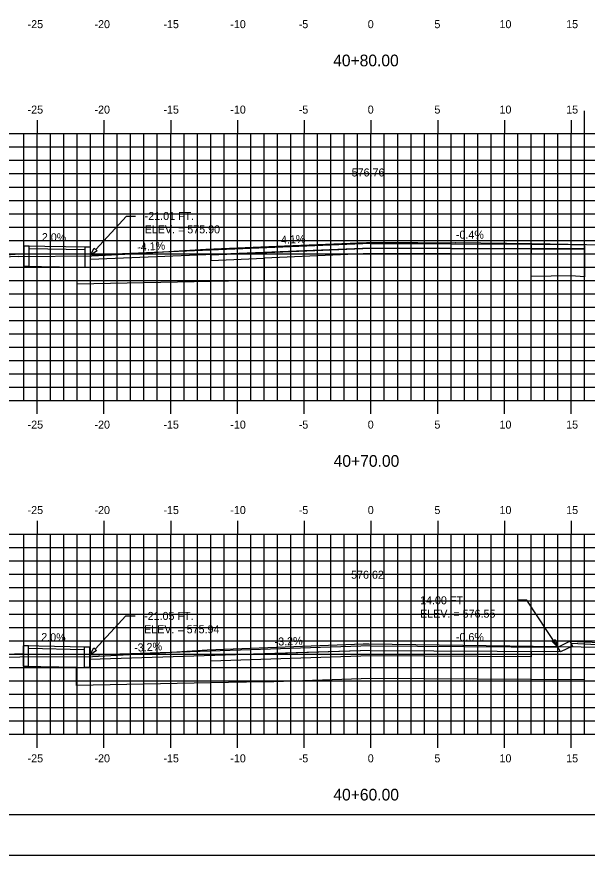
# Model space of a CAD drawing. Extents: x 1048345 to 1048515, y 781148 to 781258.
# Drawn here: x 1048401.3 to 1048444, y 781148.2 to 781211 of the extents above; entities that cross this region are included whole.
import ezdxf

# ---------------------------------------------------------------- set-up
doc = ezdxf.new("R2010")
doc.units = 0
for name, color, linetype in [('ANNOTATION', 7, 'Continuous'), ('BORDER', 7, 'Continuous'), ('D_Curb_Type1_Lt', 7, 'Continuous'), ('D_Curb_Type_5_Rt', 7, 'Continuous'), ('D_Roadway_Centerline', 7, 'Continuous'), ('D_Roadway_Centerline_Text', 7, 'Continuous'), ('D_Roadway_Edge_Shoulder', 7, 'Continuous'), ('D_Roadway_Edge_TW', 7, 'Continuous'), ('D_Roadway_Pavement', 7, 'Continuous'), ('D_Roadway_Sidewalks_Paved', 7, 'Continuous'), ('D_Roadway_SubGrade', 7, 'Continuous'), ('D_Text_Standard', 7, 'Continuous'), ('E_ROW_Line', 7, 'Continuous'), ('H_V ANNOTATION', 7, 'Continuous'), ('MAJOR', 7, 'Continuous'), ('MINOR', 7, 'Continuous'), ('PLOT BOUNDARY', 7, 'Continuous'), ('S_Roadway_Centerline', 7, 'Continuous')]:
    doc.layers.add(name, color=color, linetype=linetype)

msp = doc.modelspace()

# ---------------------------------------------------------------- linework, layer by layer
at = {"layer": 'BORDER'}
msp.add_lwpolyline([(1048352.833, 781151.252), (1048512.833, 781151.252), (1048512.833, 781256.252), (1048352.833, 781256.252)], close=True, dxfattribs=at)
at = {"layer": 'D_Curb_Type1_Lt'}
for points in [[(1048401.824, 781193.83), (1048401.824, 781192.33), (1048402.241, 781192.33), (1048402.241, 781193.83)], [(1048406.406, 781193.736), (1048406.406, 781192.236), (1048406.823, 781192.236), (1048406.823, 781193.736)], [(1048406.406, 781193.736), (1048406.406, 781192.236), (1048406.823, 781192.236), (1048406.823, 781193.736)], [(1048401.78, 781163.869), (1048401.78, 781162.369), (1048402.196, 781162.369), (1048402.196, 781163.869)], [(1048406.362, 781163.775), (1048406.362, 781162.275), (1048406.779, 781162.275), (1048406.779, 781163.775)]]:
    msp.add_lwpolyline(points, close=True, dxfattribs=at)
at = {"layer": 'D_Curb_Type_5_Rt'}
msp.add_lwpolyline([(1048441.832, 781163.792), (1048442.727, 781164.24), (1048442.913, 781163.867), (1048442.019, 781163.42)], close=True, dxfattribs=at)
at = {"layer": 'D_Roadway_Edge_Shoulder'}
for p, q in [((1048427.832, 781194.011), (1048406.824, 781193.152)), ((1048427.832, 781193.678), (1048406.825, 781192.819))]:
    msp.add_line(p, q, dxfattribs=at)
msp.add_lwpolyline([(1048439.832, 781193.963), (1048442.832, 781193.951), (1048443.832, 781193.947), (1048443.832, 781193.614), (1048442.832, 781193.618), (1048439.832, 781193.63)], close=True, dxfattribs=at)
at = {"layer": 'D_Roadway_Edge_TW'}
for p, q in [((1048427.832, 781163.874), (1048406.785, 781163.192)), ((1048427.832, 781163.541), (1048406.785, 781162.859)), ((1048427.832, 781163.874), (1048441.832, 781163.792)), ((1048427.832, 781163.541), (1048441.999, 781163.458))]:
    msp.add_line(p, q, dxfattribs=at)
msp.add_lwpolyline([(1048427.832, 781194.011), (1048439.832, 781193.963), (1048439.832, 781193.63), (1048427.832, 781193.678)], dxfattribs=at)
at = {"layer": 'D_Roadway_Pavement'}
for p, q in [((1048427.832, 781163.541), (1048415.832, 781163.152)), ((1048401.78, 781163.286), (1048396.063, 781163.02))]:
    msp.add_line(p, q, dxfattribs=at)
for points in [[(1048415.832, 781192.757), (1048415.832, 781193.174), (1048427.832, 781193.678), (1048439.832, 781193.63), (1048439.832, 781193.213), (1048427.832, 781193.261), (1048419.832, 781192.925)], [(1048439.832, 781163.471), (1048439.832, 781163.064), (1048427.832, 781163.124)], [(1048427.832, 781163.124), (1048415.832, 781162.735), (1048415.832, 781163.152)], [(1048415.832, 781162.735), (1048415.832, 781163.121)]]:
    msp.add_lwpolyline(points, dxfattribs=at)
at = {"layer": 'D_Roadway_Sidewalks_Paved'}
for points in [[(1048406.523, 781193.736), (1048401.824, 781193.83), (1048401.824, 781193.663)], [(1048406.523, 781193.736), (1048401.824, 781193.83), (1048401.824, 781193.663)], [(1048402.241, 781193.655), (1048406.406, 781193.571)], [(1048402.241, 781193.655), (1048406.406, 781193.571)], [(1048406.479, 781163.775), (1048401.78, 781163.869), (1048401.78, 781163.703)], [(1048402.196, 781163.694), (1048406.362, 781163.611)]]:
    msp.add_lwpolyline(points, dxfattribs=at)
at = {"layer": 'D_Roadway_SubGrade'}
for p, q in [((1048401.824, 781193.83), (1048401.824, 781192.33)), ((1048443.832, 781193.947), (1048443.832, 781191.521)), ((1048401.824, 781193.246), (1048397.06, 781192.89)), ((1048401.824, 781192.33), (1048405.824, 781192.25)), ((1048405.825, 781192.064), (1048405.824, 781192.25)), ((1048442.727, 781164.24), (1048446.775, 781164.052)), ((1048443.832, 781163.262), (1048443.832, 781164.054)), ((1048401.78, 781163.869), (1048401.78, 781162.369)), ((1048401.78, 781162.369), (1048405.78, 781162.289)), ((1048405.786, 781162.099), (1048405.78, 781162.289))]:
    msp.add_line(p, q, dxfattribs=at)
for points in [[(1048443.832, 781191.521), (1048442.832, 781191.595), (1048439.832, 781191.547), (1048439.832, 781193.63), (1048439.832, 781193.63), (1048442.832, 781193.618), (1048443.832, 781193.614), (1048443.832, 781193.031)], [(1048415.832, 781193.174), (1048415.832, 781192.757), (1048419.832, 781192.925), (1048419.832, 781191.259), (1048415.832, 781191.179), (1048405.825, 781190.978), (1048405.825, 781192.064)], [(1048442.814, 781164.072), (1048446.768, 781163.889)], [(1048419.832, 781161.177), (1048427.832, 781161.457), (1048443.832, 781161.364), (1048443.832, 781163.262)], [(1048419.832, 781161.177), (1048415.832, 781161.097), (1048405.786, 781160.896), (1048405.786, 781162.099)]]:
    msp.add_lwpolyline(points, dxfattribs=at)
at = {"layer": 'D_Text_Standard'}
for points in [[(1048407.219, 781193.58), (1048409.525, 781196.08), (1048410.205, 781196.08)], [(1048441.832, 781163.792), (1048439.515, 781167.292), (1048438.835, 781167.292)], [(1048407.174, 781163.62), (1048409.481, 781166.12), (1048410.161, 781166.12)]]:
    msp.add_lwpolyline(points, dxfattribs=at)
for points in [[(1048406.824, 781193.152), (1048407.112, 781193.679), (1048407.326, 781193.481)], [(1048441.832, 781163.792), (1048441.39, 781164.197), (1048441.632, 781164.358)], [(1048406.78, 781163.192), (1048407.067, 781163.718), (1048407.281, 781163.521)]]:
    msp.add_lwpolyline(points, close=True, dxfattribs=at)
at = {"layer": 'E_ROW_Line'}
msp.add_line((1048443.832, 781193.947), (1048443.832, 781203.947), dxfattribs=at)
at = {"layer": 'MAJOR'}
for p, q in [((1048402.832, 781203.254), (1048402.832, 781202.252)), ((1048407.832, 781203.254), (1048407.832, 781202.252)), ((1048412.832, 781203.254), (1048412.832, 781202.252)), ((1048417.832, 781203.254), (1048417.832, 781202.252)), ((1048422.832, 781203.254), (1048422.832, 781202.252)), ((1048427.832, 781203.254), (1048427.832, 781202.252)), ((1048432.832, 781203.254), (1048432.832, 781202.252)), ((1048437.832, 781203.254), (1048437.832, 781202.252)), ((1048442.832, 781203.254), (1048442.832, 781202.252)), ((1048357.832, 781202.252), (1048497.832, 781202.252)), ((1048357.832, 781202.252), (1048497.832, 781202.252)), ((1048357.832, 781202.252), (1048497.832, 781202.252)), ((1048402.832, 781182.252), (1048402.832, 781202.252)), ((1048402.832, 781182.252), (1048402.832, 781202.252)), ((1048407.832, 781182.252), (1048407.832, 781202.252)), ((1048407.832, 781182.252), (1048407.832, 781202.252)), ((1048412.832, 781182.252), (1048412.832, 781202.252)), ((1048412.832, 781182.252), (1048412.832, 781202.252)), ((1048417.832, 781182.252), (1048417.832, 781202.252)), ((1048417.832, 781182.252), (1048417.832, 781202.252)), ((1048422.832, 781182.252), (1048422.832, 781202.252)), ((1048422.832, 781182.252), (1048422.832, 781202.252)), ((1048427.832, 781182.252), (1048427.832, 781202.252)), ((1048427.832, 781182.252), (1048427.832, 781202.252)), ((1048432.832, 781182.252), (1048432.832, 781202.252)), ((1048432.832, 781182.252), (1048432.832, 781202.252)), ((1048437.832, 781182.252), (1048437.832, 781202.252)), ((1048437.832, 781182.252), (1048437.832, 781202.252)), ((1048442.832, 781182.252), (1048442.832, 781202.252)), ((1048442.832, 781182.252), (1048442.832, 781202.252)), ((1048357.832, 781197.252), (1048497.832, 781197.252)), ((1048357.832, 781197.252), (1048497.832, 781197.252)), ((1048357.832, 781192.252), (1048497.832, 781192.252)), ((1048357.832, 781192.252), (1048497.832, 781192.252)), ((1048357.832, 781187.252), (1048497.832, 781187.252)), ((1048357.832, 781187.252), (1048497.832, 781187.252)), ((1048357.832, 781182.252), (1048497.832, 781182.252)), ((1048357.832, 781182.252), (1048497.832, 781182.252)), ((1048357.832, 781182.252), (1048497.832, 781182.252)), ((1048402.832, 781181.25), (1048402.832, 781182.252)), ((1048407.832, 781181.25), (1048407.832, 781182.252)), ((1048412.832, 781181.25), (1048412.832, 781182.252)), ((1048417.832, 781181.25), (1048417.832, 781182.252)), ((1048422.832, 781181.25), (1048422.832, 781182.252)), ((1048427.832, 781181.25), (1048427.832, 781182.252)), ((1048432.832, 781181.25), (1048432.832, 781182.252)), ((1048437.832, 781181.25), (1048437.832, 781182.252)), ((1048442.832, 781181.25), (1048442.832, 781182.252)), ((1048402.832, 781173.254), (1048402.832, 781172.252)), ((1048407.832, 781173.254), (1048407.832, 781172.252)), ((1048412.832, 781173.254), (1048412.832, 781172.252)), ((1048417.832, 781173.254), (1048417.832, 781172.252)), ((1048422.832, 781173.254), (1048422.832, 781172.252)), ((1048427.832, 781173.254), (1048427.832, 781172.252)), ((1048432.832, 781173.254), (1048432.832, 781172.252)), ((1048437.832, 781173.254), (1048437.832, 781172.252)), ((1048442.832, 781173.254), (1048442.832, 781172.252)), ((1048357.832, 781172.252), (1048497.832, 781172.252)), ((1048357.832, 781172.252), (1048497.832, 781172.252)), ((1048402.832, 781157.252), (1048402.832, 781172.252)), ((1048407.832, 781157.252), (1048407.832, 781172.252)), ((1048412.832, 781157.252), (1048412.832, 781172.252)), ((1048417.832, 781157.252), (1048417.832, 781172.252)), ((1048422.832, 781157.252), (1048422.832, 781172.252)), ((1048427.832, 781157.252), (1048427.832, 781172.252)), ((1048432.832, 781157.252), (1048432.832, 781172.252)), ((1048437.832, 781157.252), (1048437.832, 781172.252)), ((1048442.832, 781157.252), (1048442.832, 781172.252)), ((1048357.832, 781167.252), (1048497.832, 781167.252)), ((1048357.832, 781162.252), (1048497.832, 781162.252)), ((1048357.832, 781157.252), (1048497.832, 781157.252)), ((1048357.832, 781157.252), (1048497.832, 781157.252)), ((1048402.832, 781156.25), (1048402.832, 781157.252)), ((1048407.832, 781156.25), (1048407.832, 781157.252)), ((1048412.832, 781156.25), (1048412.832, 781157.252)), ((1048417.832, 781156.25), (1048417.832, 781157.252)), ((1048422.832, 781156.25), (1048422.832, 781157.252)), ((1048427.832, 781156.25), (1048427.832, 781157.252)), ((1048432.832, 781156.25), (1048432.832, 781157.252)), ((1048437.832, 781156.25), (1048437.832, 781157.252)), ((1048442.832, 781156.25), (1048442.832, 781157.252))]:
    msp.add_line(p, q, dxfattribs=at)
at = {"layer": 'MINOR'}
for p, q in [((1048401.832, 781182.252), (1048401.832, 781202.252)), ((1048401.832, 781182.252), (1048401.832, 781202.252)), ((1048403.832, 781182.252), (1048403.832, 781202.252)), ((1048403.832, 781182.252), (1048403.832, 781202.252)), ((1048404.832, 781182.252), (1048404.832, 781202.252)), ((1048404.832, 781182.252), (1048404.832, 781202.252)), ((1048405.832, 781182.252), (1048405.832, 781202.252)), ((1048405.832, 781182.252), (1048405.832, 781202.252)), ((1048406.832, 781182.252), (1048406.832, 781202.252)), ((1048406.832, 781182.252), (1048406.832, 781202.252)), ((1048408.832, 781182.252), (1048408.832, 781202.252)), ((1048408.832, 781182.252), (1048408.832, 781202.252)), ((1048409.832, 781182.252), (1048409.832, 781202.252)), ((1048409.832, 781182.252), (1048409.832, 781202.252)), ((1048410.832, 781182.252), (1048410.832, 781202.252)), ((1048410.832, 781182.252), (1048410.832, 781202.252)), ((1048411.832, 781182.252), (1048411.832, 781202.252)), ((1048411.832, 781182.252), (1048411.832, 781202.252)), ((1048413.832, 781182.252), (1048413.832, 781202.252)), ((1048413.832, 781182.252), (1048413.832, 781202.252)), ((1048414.832, 781182.252), (1048414.832, 781202.252)), ((1048414.832, 781182.252), (1048414.832, 781202.252)), ((1048415.832, 781182.252), (1048415.832, 781202.252)), ((1048415.832, 781182.252), (1048415.832, 781202.252)), ((1048416.832, 781182.252), (1048416.832, 781202.252)), ((1048416.832, 781182.252), (1048416.832, 781202.252)), ((1048418.832, 781182.252), (1048418.832, 781202.252)), ((1048418.832, 781182.252), (1048418.832, 781202.252)), ((1048419.832, 781182.252), (1048419.832, 781202.252)), ((1048419.832, 781182.252), (1048419.832, 781202.252)), ((1048420.832, 781182.252), (1048420.832, 781202.252)), ((1048420.832, 781182.252), (1048420.832, 781202.252)), ((1048421.832, 781182.252), (1048421.832, 781202.252)), ((1048421.832, 781182.252), (1048421.832, 781202.252)), ((1048423.832, 781182.252), (1048423.832, 781202.252)), ((1048423.832, 781182.252), (1048423.832, 781202.252)), ((1048424.832, 781182.252), (1048424.832, 781202.252)), ((1048424.832, 781182.252), (1048424.832, 781202.252)), ((1048425.832, 781182.252), (1048425.832, 781202.252)), ((1048425.832, 781182.252), (1048425.832, 781202.252)), ((1048426.832, 781182.252), (1048426.832, 781202.252)), ((1048426.832, 781182.252), (1048426.832, 781202.252)), ((1048428.832, 781182.252), (1048428.832, 781202.252)), ((1048428.832, 781182.252), (1048428.832, 781202.252)), ((1048429.832, 781182.252), (1048429.832, 781202.252)), ((1048429.832, 781182.252), (1048429.832, 781202.252)), ((1048430.832, 781182.252), (1048430.832, 781202.252)), ((1048430.832, 781182.252), (1048430.832, 781202.252)), ((1048431.832, 781182.252), (1048431.832, 781202.252)), ((1048431.832, 781182.252), (1048431.832, 781202.252)), ((1048433.832, 781182.252), (1048433.832, 781202.252)), ((1048433.832, 781182.252), (1048433.832, 781202.252)), ((1048434.832, 781182.252), (1048434.832, 781202.252)), ((1048434.832, 781182.252), (1048434.832, 781202.252)), ((1048435.832, 781182.252), (1048435.832, 781202.252)), ((1048435.832, 781182.252), (1048435.832, 781202.252)), ((1048436.832, 781182.252), (1048436.832, 781202.252)), ((1048436.832, 781182.252), (1048436.832, 781202.252)), ((1048438.832, 781182.252), (1048438.832, 781202.252)), ((1048438.832, 781182.252), (1048438.832, 781202.252)), ((1048439.832, 781182.252), (1048439.832, 781202.252)), ((1048439.832, 781182.252), (1048439.832, 781202.252)), ((1048440.832, 781182.252), (1048440.832, 781202.252)), ((1048440.832, 781182.252), (1048440.832, 781202.252)), ((1048441.832, 781182.252), (1048441.832, 781202.252)), ((1048441.832, 781182.252), (1048441.832, 781202.252)), ((1048443.832, 781182.252), (1048443.832, 781202.252)), ((1048443.832, 781182.252), (1048443.832, 781202.252)), ((1048357.832, 781201.252), (1048497.832, 781201.252)), ((1048357.832, 781201.252), (1048497.832, 781201.252)), ((1048357.832, 781200.252), (1048497.832, 781200.252)), ((1048357.832, 781200.252), (1048497.832, 781200.252)), ((1048357.832, 781199.252), (1048497.832, 781199.252)), ((1048357.832, 781199.252), (1048497.832, 781199.252)), ((1048357.832, 781198.252), (1048497.832, 781198.252)), ((1048357.832, 781198.252), (1048497.832, 781198.252)), ((1048357.832, 781196.252), (1048497.832, 781196.252)), ((1048357.832, 781196.252), (1048497.832, 781196.252)), ((1048357.832, 781195.252), (1048497.832, 781195.252)), ((1048357.832, 781195.252), (1048497.832, 781195.252)), ((1048357.832, 781194.252), (1048497.832, 781194.252)), ((1048357.832, 781194.252), (1048497.832, 781194.252)), ((1048357.832, 781193.252), (1048497.832, 781193.252)), ((1048357.832, 781193.252), (1048497.832, 781193.252)), ((1048357.832, 781191.252), (1048497.832, 781191.252)), ((1048357.832, 781191.252), (1048497.832, 781191.252)), ((1048357.832, 781190.252), (1048497.832, 781190.252)), ((1048357.832, 781190.252), (1048497.832, 781190.252)), ((1048357.832, 781189.252), (1048497.832, 781189.252)), ((1048357.832, 781189.252), (1048497.832, 781189.252)), ((1048357.832, 781188.252), (1048497.832, 781188.252)), ((1048357.832, 781188.252), (1048497.832, 781188.252)), ((1048357.832, 781186.252), (1048497.832, 781186.252)), ((1048357.832, 781186.252), (1048497.832, 781186.252)), ((1048357.832, 781185.252), (1048497.832, 781185.252)), ((1048357.832, 781185.252), (1048497.832, 781185.252)), ((1048357.832, 781184.252), (1048497.832, 781184.252)), ((1048357.832, 781184.252), (1048497.832, 781184.252)), ((1048357.832, 781183.252), (1048497.832, 781183.252)), ((1048357.832, 781183.252), (1048497.832, 781183.252)), ((1048401.832, 781157.252), (1048401.832, 781172.252)), ((1048403.832, 781157.252), (1048403.832, 781172.252)), ((1048404.832, 781157.252), (1048404.832, 781172.252)), ((1048405.832, 781157.252), (1048405.832, 781172.252)), ((1048406.832, 781157.252), (1048406.832, 781172.252)), ((1048408.832, 781157.252), (1048408.832, 781172.252)), ((1048409.832, 781157.252), (1048409.832, 781172.252)), ((1048410.832, 781157.252), (1048410.832, 781172.252)), ((1048411.832, 781157.252), (1048411.832, 781172.252)), ((1048413.832, 781157.252), (1048413.832, 781172.252)), ((1048414.832, 781157.252), (1048414.832, 781172.252)), ((1048415.832, 781157.252), (1048415.832, 781172.252)), ((1048416.832, 781157.252), (1048416.832, 781172.252)), ((1048418.832, 781157.252), (1048418.832, 781172.252)), ((1048419.832, 781157.252), (1048419.832, 781172.252)), ((1048420.832, 781157.252), (1048420.832, 781172.252)), ((1048421.832, 781157.252), (1048421.832, 781172.252)), ((1048423.832, 781157.252), (1048423.832, 781172.252)), ((1048424.832, 781157.252), (1048424.832, 781172.252)), ((1048425.832, 781157.252), (1048425.832, 781172.252)), ((1048426.832, 781157.252), (1048426.832, 781172.252)), ((1048428.832, 781157.252), (1048428.832, 781172.252)), ((1048429.832, 781157.252), (1048429.832, 781172.252)), ((1048430.832, 781157.252), (1048430.832, 781172.252)), ((1048431.832, 781157.252), (1048431.832, 781172.252)), ((1048433.832, 781157.252), (1048433.832, 781172.252)), ((1048434.832, 781157.252), (1048434.832, 781172.252)), ((1048435.832, 781157.252), (1048435.832, 781172.252)), ((1048436.832, 781157.252), (1048436.832, 781172.252)), ((1048438.832, 781157.252), (1048438.832, 781172.252)), ((1048439.832, 781157.252), (1048439.832, 781172.252)), ((1048440.832, 781157.252), (1048440.832, 781172.252)), ((1048441.832, 781157.252), (1048441.832, 781172.252)), ((1048443.832, 781157.252), (1048443.832, 781172.252)), ((1048357.832, 781171.252), (1048497.832, 781171.252)), ((1048357.832, 781170.252), (1048497.832, 781170.252)), ((1048357.832, 781169.252), (1048497.832, 781169.252)), ((1048357.832, 781168.252), (1048497.832, 781168.252)), ((1048357.832, 781166.252), (1048497.832, 781166.252)), ((1048357.832, 781165.252), (1048497.832, 781165.252)), ((1048357.832, 781164.252), (1048497.832, 781164.252)), ((1048357.832, 781163.252), (1048497.832, 781163.252)), ((1048357.832, 781161.252), (1048497.832, 781161.252)), ((1048357.832, 781160.252), (1048497.832, 781160.252)), ((1048357.832, 781159.252), (1048497.832, 781159.252)), ((1048357.832, 781158.252), (1048497.832, 781158.252))]:
    msp.add_line(p, q, dxfattribs=at)
at = {"layer": 'PLOT BOUNDARY'}
msp.add_lwpolyline([(1048344.739, 781148.193), (1048514.739, 781148.193), (1048514.739, 781258.193), (1048344.739, 781258.193)], close=True, dxfattribs=at)
at = {"layer": 'S_Roadway_Centerline'}
for points in [[(1048378.404, 781193.971), (1048380.444, 781192.878), (1048381.518, 781192.487), (1048383.629, 781192.368), (1048383.98, 781192.382), (1048392.669, 781192.719), (1048401.451, 781193.061), (1048401.471, 781193.059), (1048406.922, 781193.087), (1048409.89, 781193.252), (1048415.467, 781193.603), (1048421.353, 781193.835), (1048427.506, 781194.095), (1048431.344, 781194.1), (1048434.132, 781194.08), (1048434.162, 781194.088), (1048439.882, 781194.008), (1048443.963, 781193.943), (1048453.31, 781193.879), (1048463.018, 781193.897), (1048464.051, 781193.889), (1048465.593, 781193.896), (1048488.39, 781193.918), (1048497.832, 781193.927)], [(1048384.638, 781163.971), (1048384.708, 781163.934), (1048387.982, 781162.741), (1048388.35, 781162.72), (1048395.158, 781162.984), (1048395.608, 781163.002), (1048396.063, 781163.02), (1048396.064, 781163.02), (1048406.97, 781163.076), (1048412.908, 781163.406), (1048415.553, 781163.573), (1048427.238, 781164.033), (1048427.497, 781164.041), (1048427.683, 781164.038), (1048439.979, 781163.865), (1048448.984, 781163.722)]]:
    msp.add_lwpolyline(points, dxfattribs=at)

# ---------------------------------------------------------------- texts
at = {"layer": 'ANNOTATION'}
for s, height, rotation, p in [('-0.4%', 0.6, 359.77082, (1048434.191, 781194.386)), ('2.0%', 0.6, 358.85424, (1048403.177, 781194.203)), ('-4.1%', 0.6, 2.40501, (1048420.839, 781193.986)), ('-4.1%', 0.6, 3.43363, (1048410.342, 781193.447)), ('0.4%', 0.01, 359.77082, (1048433.816, 781193.992)), ('2.0%', 0.6, 358.85424, (1048403.133, 781164.242)), ('-0.6%', 0.6, 359.71352, (1048434.192, 781164.242)), ('-3.2%', 0.6, 2.86241, (1048410.11, 781163.437)), ('-3.2%', 0.6, 2.00453, (1048420.628, 781163.891)), ('3.2%', 0.01, 1.85477, (1048417.291, 781163.537)), ('0.6%', 0.01, 359.6661, (1048434.816, 781163.838))]:
    msp.add_text(s, height=height, rotation=rotation, dxfattribs=at).set_placement(p)
at = {"layer": 'D_Roadway_Centerline'}
for s, p in [('C', (1048427.827, 781194.011)), ('L', (1048427.832, 781194.004)), ('C', (1048427.827, 781163.874)), ('L', (1048427.832, 781163.867))]:
    msp.add_text(s, height=0.0146, dxfattribs=at).set_placement(p)
at = {"layer": 'D_Roadway_Centerline_Text'}
for s, p in [('576.76', (1048426.387, 781199.043)), ('576.62', (1048426.342, 781168.906))]:
    msp.add_text(s, height=0.6, dxfattribs=at).set_placement(p)
at = {"layer": 'D_Text_Standard'}
for s, p in [('-21.01 FT.', (1048410.885, 781195.78)), ('ELEV. = 575.90', (1048410.885, 781194.78)), ('14.00 FT.', (1048431.51, 781166.992)), ('ELEV. = 576.55', (1048431.51, 781165.992)), ('-21.05 FT.', (1048410.841, 781165.82)), ('ELEV. = 575.94', (1048410.841, 781164.82))]:
    msp.add_text(s, height=0.6, dxfattribs=at).set_placement(p)
at = {"layer": 'H_V ANNOTATION'}
for s, height, p in [('-25', 0.6, (1048402.118, 781210.152)), ('-20', 0.6, (1048407.126, 781210.152)), ('-15', 0.6, (1048412.289, 781210.152)), ('-10', 0.6, (1048417.297, 781210.152)), ('-5', 0.6, (1048422.423, 781210.152)), ('0', 0.6, (1048427.591, 781210.152)), ('5', 0.6, (1048432.583, 781210.152)), ('10', 0.6, (1048437.458, 781210.152)), ('15', 0.6, (1048442.45, 781210.152)), ('40+80.00', 0.875, (1048425, 781207.295)), ('-25', 0.6, (1048402.118, 781203.752)), ('-20', 0.6, (1048407.126, 781203.752)), ('-15', 0.6, (1048412.289, 781203.752)), ('-10', 0.6, (1048417.297, 781203.752)), ('-5', 0.6, (1048422.423, 781203.752)), ('0', 0.6, (1048427.591, 781203.752)), ('5', 0.6, (1048432.583, 781203.752)), ('10', 0.6, (1048437.458, 781203.752)), ('15', 0.6, (1048442.45, 781203.752)), ('-25', 0.6, (1048402.118, 781180.152)), ('-20', 0.6, (1048407.126, 781180.152)), ('-15', 0.6, (1048412.289, 781180.152)), ('-10', 0.6, (1048417.297, 781180.152)), ('-5', 0.6, (1048422.423, 781180.152)), ('0', 0.6, (1048427.591, 781180.152)), ('5', 0.6, (1048432.583, 781180.152)), ('10', 0.6, (1048437.458, 781180.152)), ('15', 0.6, (1048442.45, 781180.152)), ('40+70.00', 0.875, (1048425.039, 781177.295)), ('-25', 0.6, (1048402.118, 781173.752)), ('-20', 0.6, (1048407.126, 781173.752)), ('-15', 0.6, (1048412.289, 781173.752)), ('-10', 0.6, (1048417.297, 781173.752)), ('-5', 0.6, (1048422.423, 781173.752)), ('0', 0.6, (1048427.591, 781173.752)), ('5', 0.6, (1048432.583, 781173.752)), ('10', 0.6, (1048437.458, 781173.752)), ('15', 0.6, (1048442.45, 781173.752)), ('-25', 0.6, (1048402.118, 781155.152)), ('-20', 0.6, (1048407.126, 781155.152)), ('-15', 0.6, (1048412.289, 781155.152)), ('-10', 0.6, (1048417.297, 781155.152)), ('-5', 0.6, (1048422.423, 781155.152)), ('0', 0.6, (1048427.591, 781155.152)), ('5', 0.6, (1048432.583, 781155.152)), ('10', 0.6, (1048437.458, 781155.152)), ('15', 0.6, (1048442.45, 781155.152)), ('40+60.00', 0.875, (1048425.016, 781152.295))]:
    msp.add_text(s, height=height, dxfattribs=at).set_placement(p)
at = {"layer": 'S_Roadway_Centerline'}
for s, p in [('L', (1048427.497, 781194.088)), ('C', (1048427.5, 781194.095)), ('L', (1048427.489, 781164.034)), ('C', (1048427.492, 781164.041))]:
    msp.add_text(s, height=0.0146, dxfattribs=at).set_placement(p)

doc.saveas('drawing.dxf')
